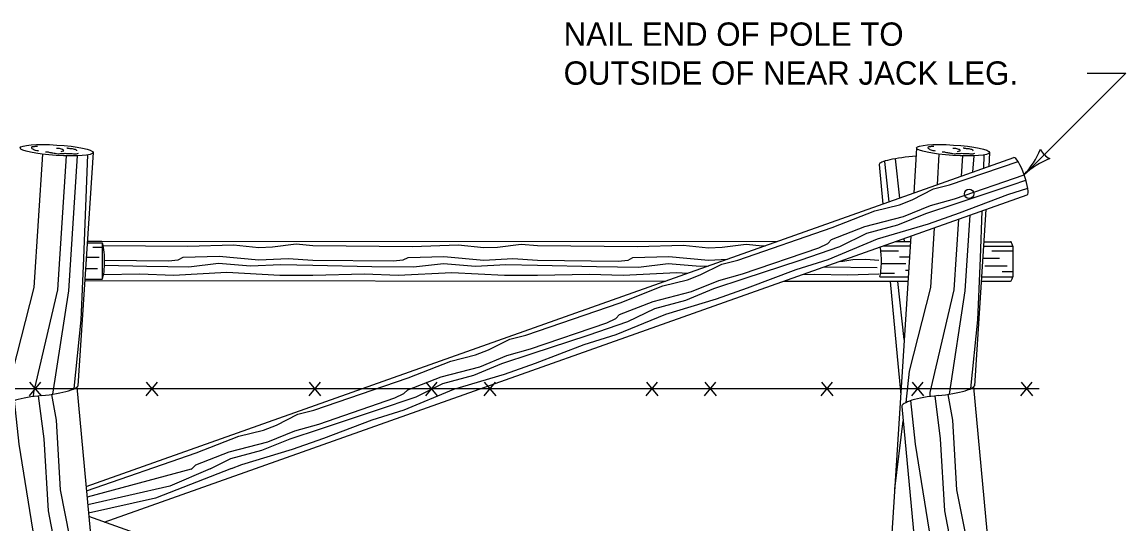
# Model space of a CAD drawing. Extents: x 49991.4 to 50021, y 49987.6 to 50011.4.
# Drawn here: x 50012.065 to 50014.903, y 49992.027 to 49993.316 of the extents above; entities that cross this region are included whole.
import ezdxf

# ---------------------------------------------------------------- set-up
doc = ezdxf.new("R2010")
doc.units = 0
for name, color, linetype in [('Level 1', 7, 'Continuous'), ('Level 2', 7, 'Continuous'), ('Level 3', 7, 'Continuous')]:
    doc.layers.add(name, color=color, linetype=linetype)

msp = doc.modelspace()

# ---------------------------------------------------------------- linework, layer by layer
at = {"layer": 'Level 1'}
for p, q in [((50014.3649, 49992.9922), (50014.3574, 49992.8762)), ((50012.2481, 49992.9807), (50012.2091, 49992.3817)), ((50012.2301, 49992.1229), (50014.6152, 49992.9675)), ((50014.5526, 49992.9807), (50014.5503, 49992.9445)), ((50014.2689, 49992.9502), (50014.2784, 49992.8482)), ((50012.2763, 49992.0316), (50014.649, 49992.8718)), ((50014.5431, 49992.8343), (50014.5136, 49992.3817)), ((50014.3503, 49992.766), (50014.2579, 49991.3299)), ((50012.233, 49992.749), (50012.2713, 49992.749)), ((50012.2333, 49992.7531), (50012.27, 49992.7531)), ((50012.2473, 49992.7371), (50012.2714, 49992.7371)), ((50012.27, 49992.7531), (50014.0066, 49992.752)), ((50012.2713, 49992.749), (50012.2716, 49992.6555)), ((50014.2786, 49992.7406), (50014.3487, 49992.7406)), ((50014.3101, 49992.7518), (50014.3494, 49992.7517)), ((50014.537, 49992.7404), (50014.6122, 49992.7404)), ((50014.5377, 49992.7516), (50014.606, 49992.7516)), ((50014.6122, 49992.7404), (50014.6122, 49992.6613)), ((50012.2306, 49992.7117), (50012.2638, 49992.7117)), ((50014.2727, 49992.7285), (50014.318, 49992.7284)), ((50014.3212, 49992.7124), (50014.347, 49992.7123)), ((50014.5349, 49992.7092), (50014.5783, 49992.7091)), ((50014.5581, 49992.728), (50014.6122, 49992.728)), ((50012.2287, 49992.6828), (50012.259, 49992.6828)), ((50014.2744, 49992.6956), (50014.3376, 49992.6956)), ((50014.5407, 49992.6894), (50014.5981, 49992.6893)), ((50012.2267, 49992.6516), (50013.7205, 49992.6506)), ((50012.2269, 49992.6556), (50012.2717, 49992.6556)), ((50014.0239, 49992.6504), (50014.3429, 49992.6502)), ((50014.2703, 49992.6615), (50014.3443, 49992.6614)), ((50014.2722, 49992.6705), (50014.3082, 49992.6705)), ((50014.3362, 49992.6782), (50014.3455, 49992.6782)), ((50014.5311, 49992.6501), (50014.6063, 49992.6501)), ((50014.5318, 49992.6613), (50014.6122, 49992.6613)), ((50014.5852, 49992.6747), (50014.6122, 49992.6747)), ((50014.297, 49992.649), (50014.3148, 49992.4569)), ((50014.3148, 49992.4569), (50014.324, 49992.3579)), ((50010.4473, 49992.3743), (50012.6961, 49992.3743)), ((50012.0842, 49992.3561), (50012.1136, 49992.3908)), ((50012.1149, 49992.3561), (50012.0856, 49992.3908)), ((50012.2063, 49992.3783), (50012.3358, 49990.9877)), ((50012.3842, 49992.3561), (50012.4136, 49992.3908)), ((50012.4149, 49992.3561), (50012.3856, 49992.3908)), ((50012.6961, 49992.3743), (50014.6799, 49992.3743)), ((50012.803, 49992.3561), (50012.8324, 49992.3908)), ((50012.8337, 49992.3561), (50012.8044, 49992.3908)), ((50013.103, 49992.3561), (50013.1324, 49992.3908)), ((50013.1337, 49992.3561), (50013.1044, 49992.3908)), ((50013.253, 49992.3561), (50013.2824, 49992.3908)), ((50013.2837, 49992.3561), (50013.2544, 49992.3908)), ((50013.6697, 49992.3561), (50013.699, 49992.3908)), ((50013.7004, 49992.3561), (50013.671, 49992.3908)), ((50013.8197, 49992.3561), (50013.849, 49992.3908)), ((50013.8504, 49992.3561), (50013.821, 49992.3908)), ((50014.1197, 49992.3561), (50014.149, 49992.3908)), ((50014.1504, 49992.3561), (50014.121, 49992.3908)), ((50014.3526, 49992.3561), (50014.382, 49992.3908)), ((50014.3833, 49992.3561), (50014.354, 49992.3908)), ((50014.5108, 49992.3783), (50014.6403, 49990.9877)), ((50014.633, 49992.3561), (50014.6624, 49992.3908)), ((50014.6637, 49992.3561), (50014.6344, 49992.3908)), ((50014.3268, 49992.3281), (50014.4534, 49990.9698)), ((50012.6039, 49992.1688), (50012.4084, 49992.0928)), ((50012.5488, 49992.168), (50012.4455, 49992.1236)), ((50012.4999, 49992.1673), (50012.2326, 49992.0951)), ((50012.4455, 49992.1236), (50012.2345, 49992.0755)), ((50012.4084, 49992.0928), (50012.2365, 49992.054)), ((50014.0306, 49991.4104), (50012.2373, 49992.0454))]:
    msp.add_line(p, q, dxfattribs=at)
for points in [[(50012.0338, 49992.3388), (50012.042, 49992.419), (50012.0969, 49992.6341), (50012.1188, 49992.9762)], [(50012.0949, 49992.3538), (50012.0953, 49992.3639), (50012.157, 49992.6279), (50012.1792, 49992.972)], [(50012.1448, 49992.3598), (50012.1854, 49992.6251), (50012.2079, 49992.9722)], [(50012.1995, 49992.3743), (50012.2175, 49992.5508), (50012.2243, 49992.7092), (50012.2344, 49992.9747)], [(50014.3214, 49992.8634), (50014.3105, 49992.964)], [(50014.4183, 49992.8977), (50014.4233, 49992.9762)], [(50014.4804, 49992.9197), (50014.4837, 49992.972)], [(50014.5097, 49992.9301), (50014.5125, 49992.9722)], [(50014.5376, 49992.94), (50014.539, 49992.9747)], [(50014.2946, 49992.854), (50014.2833, 49992.9577)], [(50014.4498, 49992.8974), (50014.6256, 49992.9578)], [(50014.4624, 49992.8619), (50014.6413, 49992.9233)], [(50014.4666, 49992.8499), (50014.6107, 49992.8973), (50014.6459, 49992.9094)], [(50013.905, 49992.7045), (50014.1475, 49992.7878), (50014.2572, 49992.8308), (50014.3207, 49992.8465), (50014.3538, 49992.8595), (50014.4086, 49992.8871), (50014.4498, 49992.8974)], [(50014.4752, 49992.8256), (50014.5997, 49992.8731), (50014.6507, 49992.889)], [(50013.9175, 49992.669), (50014.1133, 49992.7362), (50014.1364, 49992.7471), (50014.1463, 49992.7574), (50014.2321, 49992.7906), (50014.3315, 49992.8162), (50014.4009, 49992.8449), (50014.4624, 49992.8619)], [(50013.9218, 49992.657), (50014.0659, 49992.7044), (50014.1678, 49992.7392), (50014.2368, 49992.7733), (50014.3166, 49992.7946), (50014.3888, 49992.8243), (50014.4666, 49992.8499)], [(50013.9305, 49992.6327), (50014.0549, 49992.6801), (50014.1375, 49992.706), (50014.2647, 49992.7585), (50014.3953, 49992.7973), (50014.4752, 49992.8256)], [(50014.504, 49992.3743), (50014.522, 49992.5508), (50014.5289, 49992.7092), (50014.5335, 49992.8309)], [(50014.3994, 49992.3538), (50014.3998, 49992.3639), (50014.4615, 49992.6279), (50014.4732, 49992.8095)], [(50014.4494, 49992.3598), (50014.49, 49992.6251), (50014.5026, 49992.8199)], [(50014.3383, 49992.3388), (50014.3465, 49992.419), (50014.4014, 49992.6341), (50014.4112, 49992.7876)], [(50012.2738, 49992.7419), (50012.4912, 49992.7397), (50012.6088, 49992.7434), (50012.6741, 49992.737), (50012.7095, 49992.7383), (50012.7704, 49992.7459), (50012.8127, 49992.7418)], [(50012.8127, 49992.7418), (50013.0691, 49992.7393), (50013.1868, 49992.7431), (50013.252, 49992.7366), (50013.2874, 49992.7379), (50013.3483, 49992.7455), (50013.3907, 49992.7415)], [(50013.3907, 49992.7415), (50013.6472, 49992.7389), (50013.7648, 49992.7427), (50013.83, 49992.7362), (50013.8654, 49992.7375), (50013.9264, 49992.7452), (50013.9687, 49992.7411)], [(50013.9687, 49992.7411), (50013.9755, 49992.7409)], [(50014.3335, 49992.7517), (50014.3326, 49992.7598)], [(50012.2775, 49992.7042), (50012.4416, 49992.7025), (50012.467, 49992.705), (50012.4798, 49992.7115), (50012.5718, 49992.714), (50012.6739, 49992.7049), (50012.7491, 49992.7087), (50012.8126, 49992.7042)], [(50012.8126, 49992.7042), (50013.0195, 49992.7021), (50013.045, 49992.7047), (50013.0578, 49992.7111), (50013.1498, 49992.7137), (50013.252, 49992.7045), (50013.327, 49992.7083), (50013.3906, 49992.7038)], [(50013.3906, 49992.7038), (50013.5975, 49992.7017), (50013.6231, 49992.7042), (50013.6358, 49992.7107), (50013.7278, 49992.7133), (50013.83, 49992.7042), (50013.8786, 49992.7066)], [(50012.2773, 49992.6909), (50012.3863, 49992.6884), (50012.494, 49992.6871), (50012.5704, 49992.6962), (50012.6527, 49992.6895), (50012.7307, 49992.6933), (50012.8126, 49992.6914)], [(50012.8126, 49992.6914), (50012.9642, 49992.688), (50013.0719, 49992.6866), (50013.1484, 49992.6958), (50013.2307, 49992.6891), (50013.3086, 49992.6929), (50013.3906, 49992.6911)], [(50013.3601, 49992.5115), (50013.6028, 49992.5949), (50013.7124, 49992.6378), (50013.776, 49992.6536), (50013.8089, 49992.6666), (50013.8638, 49992.6941), (50013.905, 49992.7045)], [(50013.3906, 49992.6911), (50013.5423, 49992.6876), (50013.65, 49992.6863), (50013.7265, 49992.6954), (50013.8087, 49992.6887), (50013.8307, 49992.6898)], [(50014.1276, 49992.6872), (50014.2639, 49992.6854)], [(50014.1679, 49992.7014), (50014.1755, 49992.7013), (50014.2007, 49992.7055), (50014.2341, 49992.7064), (50014.2681, 49992.7045)], [(50012.2748, 49992.6671), (50012.3679, 49992.6691), (50012.4543, 49992.666), (50012.5918, 49992.6729), (50012.7278, 49992.6658), (50012.8126, 49992.6657)], [(50012.8126, 49992.6657), (50012.9458, 49992.6688), (50013.0323, 49992.6655), (50013.1698, 49992.6725), (50013.3058, 49992.6654), (50013.3906, 49992.6653)], [(50013.3727, 49992.476), (50013.5685, 49992.5433), (50013.5917, 49992.5542), (50013.6015, 49992.5645), (50013.6873, 49992.5977), (50013.7866, 49992.6233), (50013.8562, 49992.6519), (50013.9175, 49992.669)], [(50013.377, 49992.4641), (50013.521, 49992.5115), (50013.6229, 49992.5463), (50013.692, 49992.5804), (50013.7717, 49992.6017), (50013.8439, 49992.6313), (50013.9218, 49992.657)], [(50013.3906, 49992.6653), (50013.5239, 49992.6684), (50013.6102, 49992.6652), (50013.7477, 49992.6722), (50013.777, 49992.6706)], [(50014.0716, 49992.6673), (50014.1018, 49992.668), (50014.1881, 49992.6665), (50014.2677, 49992.6688)], [(50013.3855, 49992.4398), (50013.5101, 49992.4872), (50013.5926, 49992.5131), (50013.7199, 49992.5656), (50013.8505, 49992.6044), (50013.9305, 49992.6327)], [(50014.3332, 49992.5), (50014.317, 49992.649)], [(50012.8153, 49992.3186), (50013.058, 49992.402), (50013.1675, 49992.4449), (50013.2311, 49992.4606), (50013.2641, 49992.4736), (50013.319, 49992.5012), (50013.3601, 49992.5115)], [(50012.8279, 49992.2831), (50013.0236, 49992.3503), (50013.0469, 49992.3613), (50013.0567, 49992.3715), (50013.1425, 49992.4048), (50013.2418, 49992.4304), (50013.3114, 49992.459), (50013.3727, 49992.476)], [(50012.8322, 49992.271), (50012.9762, 49992.3186), (50013.0782, 49992.3533), (50013.1471, 49992.3874), (50013.2269, 49992.4087), (50013.2991, 49992.4384), (50013.377, 49992.4641)], [(50012.8407, 49992.2469), (50012.9653, 49992.2943), (50013.0478, 49992.3201), (50013.1751, 49992.3726), (50013.3056, 49992.4114), (50013.3855, 49992.4398)], [(50012.1909, 49990.9899), (50012.1576, 49991.3822), (50012.128, 49991.5856), (50012.1092, 49991.9121), (50012.0578, 49992.2317), (50012.0457, 49992.3433)], [(50012.255, 49990.9988), (50012.1983, 49991.4307), (50012.1677, 49991.6848), (50012.1698, 49991.8677), (50012.133, 49992.0604), (50012.1221, 49992.2455), (50012.1078, 49992.3553)], [(50012.2845, 49990.9996), (50012.2175, 49991.5649), (50012.217, 49991.6258), (50012.229, 49991.6576), (50012.2116, 49991.8755), (50012.1639, 49992.1145), (50012.1538, 49992.2929), (50012.1418, 49992.3594)], [(50014.4954, 49990.9899), (50014.4621, 49991.3822), (50014.4325, 49991.5856), (50014.4137, 49991.9121), (50014.3623, 49992.2317), (50014.3502, 49992.3433)], [(50014.5596, 49990.9988), (50014.5028, 49991.4307), (50014.4722, 49991.6848), (50014.4743, 49991.8677), (50014.4375, 49992.0604), (50014.4266, 49992.2455), (50014.4123, 49992.3553)], [(50014.589, 49990.9996), (50014.5221, 49991.5649), (50014.5216, 49991.6258), (50014.5335, 49991.6576), (50014.5161, 49991.8755), (50014.4685, 49992.1145), (50014.4583, 49992.2929), (50014.4464, 49992.3594)], [(50012.2311, 49992.1121), (50012.5131, 49992.2091), (50012.6227, 49992.2519), (50012.6863, 49992.2676), (50012.7193, 49992.2806), (50012.7741, 49992.3083), (50012.8153, 49992.3186)], [(50012.4999, 49992.1673), (50012.502, 49992.1683), (50012.5118, 49992.1786), (50012.5976, 49992.2119), (50012.697, 49992.2374), (50012.7665, 49992.2661), (50012.8279, 49992.2831)], [(50014.3086, 49992.117), (50014.3302, 49992.2918)], [(50012.5488, 49992.168), (50012.6023, 49992.1946), (50012.6821, 49992.2158), (50012.7543, 49992.2454), (50012.8322, 49992.271)], [(50012.6039, 49992.1688), (50012.6303, 49992.1797), (50012.7608, 49992.2185), (50012.8407, 49992.2469)]]:
    msp.add_lwpolyline(points, dxfattribs=at)
msp.add_circle((50014.4997, 49992.8744), 0.012, dxfattribs=at)
for centre in [(50012.1542, 49992.9865), (50014.4587, 49992.9865)]:
    msp.add_ellipse(centre, major_axis=(0.0937, -0.0058), ratio=0.143064, dxfattribs=at)
for centre, major_axis, ratio, start_param, end_param in [((50014.3625, 49992.9574), (0.0936, 0.0072), 0.143064, 1.548914, 3.140392), ((50014.6321, 49992.9196), (-0.0169, 0.0479), 0.196346, 3.14159, 6.28209), ((50012.2676, 49992.7019), (0, 0.0508), 0.196346, 3.558661, 5.901691), ((50014.2634, 49992.7011), (0, 0.0508), 0.217807, 3.819255, 5.52486), ((50014.6059, 49992.7008), (0, 0.0508), 0.196346, 5.605404, 6.28209), ((50014.6059, 49992.7008), (0, 0.0508), 0.196346, 3.14159, 3.821196), ((50012.1167, 49992.3754), (0.0932, 0.0089), 0.201992, 4.679863, 6.355951), ((50014.4212, 49992.3754), (0.0932, 0.0089), 0.201992, 4.679863, 6.355951), ((50012.1158, 49992.3372), (0.0934, 0.0089), 0.201542, 1.555621, 3.157543), ((50014.4203, 49992.3372), (0.0934, 0.0089), 0.201542, 1.555621, 3.157543)]:
    msp.add_ellipse(centre, major_axis=major_axis, ratio=ratio, start_param=start_param, end_param=end_param, dxfattribs=at)
for points in [[(50012.1088, 49992.9841), (50012.1033, 49992.9853), (50012.0975, 49992.9866), (50012.0932, 49992.9892), (50012.0902, 49992.9919), (50012.0907, 49992.9951), (50012.0947, 49992.996), (50012.0991, 49992.9969), (50012.105, 49992.9966)], [(50012.1658, 49992.9833), (50012.1713, 49992.985), (50012.1728, 49992.9853), (50012.1702, 49992.9881), (50012.1692, 49992.9887), (50012.1639, 49992.9903), (50012.1587, 49992.9909), (50012.1544, 49992.9909), (50012.1539, 49992.9913)], [(50012.1802, 49992.9927), (50012.1825, 49992.9919), (50012.1859, 49992.9916), (50012.1902, 49992.9909), (50012.1943, 49992.9908), (50012.1995, 49992.9895), (50012.2017, 49992.9892), (50012.2041, 49992.9878), (50012.205, 49992.9864), (50012.2055, 49992.9853), (50012.2055, 49992.985)], [(50014.4133, 49992.9841), (50014.4078, 49992.9853), (50014.4021, 49992.9866), (50014.3977, 49992.9892), (50014.3947, 49992.9919), (50014.3952, 49992.9951), (50014.3992, 49992.996), (50014.4036, 49992.9969), (50014.4095, 49992.9966)], [(50014.4704, 49992.9833), (50014.4759, 49992.985), (50014.4773, 49992.9853), (50014.4747, 49992.9881), (50014.4737, 49992.9887), (50014.4684, 49992.9903), (50014.4633, 49992.9909), (50014.4589, 49992.9909), (50014.4584, 49992.9913)], [(50014.4847, 49992.9927), (50014.4871, 49992.9919), (50014.4905, 49992.9916), (50014.4948, 49992.9909), (50014.4988, 49992.9908), (50014.504, 49992.9895), (50014.5063, 49992.9892), (50014.5087, 49992.9878), (50014.5095, 49992.9864), (50014.51, 49992.9853), (50014.51, 49992.985)], [(50012.1258, 49992.9825), (50012.1311, 49992.9825), (50012.1339, 49992.9815), (50012.1398, 49992.9807), (50012.1447, 49992.9796), (50012.1504, 49992.9786), (50012.157, 49992.9776), (50012.1605, 49992.9776), (50012.1701, 49992.9782), (50012.1702, 49992.9782), (50012.1763, 49992.9786), (50012.1836, 49992.9782), (50012.1943, 49992.9782), (50012.2002, 49992.9772), (50012.2055, 49992.9776), (50012.2103, 49992.9789)], [(50014.4303, 49992.9825), (50014.4356, 49992.9825), (50014.4384, 49992.9815), (50014.4444, 49992.9807), (50014.4492, 49992.9796), (50014.4549, 49992.9786), (50014.4615, 49992.9776), (50014.4651, 49992.9776), (50014.4746, 49992.9782), (50014.4747, 49992.9782), (50014.4808, 49992.9786), (50014.4881, 49992.9782), (50014.4988, 49992.9782), (50014.5048, 49992.9772), (50014.51, 49992.9776), (50014.5148, 49992.9789)]]:
    msp.add_spline(points, degree=3, dxfattribs=at)
at = {"layer": 'Level 3'}
msp.add_lwpolyline([(50014.803, 49993.1847), (50014.903, 49993.1847), (50014.6414, 49992.9233)], dxfattribs=at)
for centre, radius, start, end in [((50014.4688, 49993.0799), 0.233, 317.7971, 337.0469), ((50014.7919, 49992.7597), 0.2223, 112.4258, 132.6093), ((50014.7321, 49993.014), 0.0548, 207.1086, 242.8309)]:
    msp.add_arc(centre, radius, start, end, dxfattribs=at)

# ---------------------------------------------------------------- texts
at = {"layer": 'Level 2'}
for s, p in [('NAIL END OF POLE TO', (50013.4576, 49993.2547)), ('OUTSIDE OF NEAR JACK LEG.', (50013.4576, 49993.1547))]:
    msp.add_text(s, height=0.06, dxfattribs=at).set_placement(p)

doc.saveas('drawing.dxf')
